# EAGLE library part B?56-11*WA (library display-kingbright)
14.22mm (0.56INCH) THREE DIGIT NUMERIC DISPLAY Source: http://www.kingbright.com .. BA56-11EWA(Ver1189474895.pdf
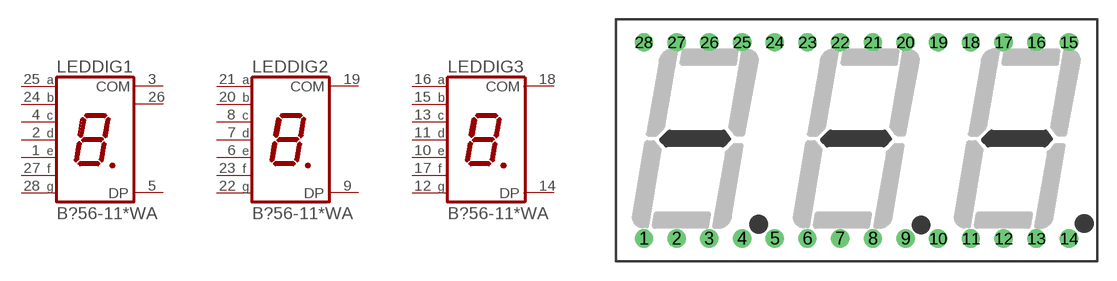
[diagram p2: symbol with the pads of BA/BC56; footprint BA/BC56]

Designator prefix LED; gates DIG2=7SEG-LED-COM1 DIG3=7SEG-LED-COM1 DIG1=7SEG-LED-COM2

## BA56-11EWA (OC_FARNELL: unknown; OC_NEWARK: unknown), BA56-11GWA (OC_FARNELL: unknown; OC_NEWARK: unknown), BA56-11SRWA (OC_FARNELL: unknown; OC_NEWARK: unknown), BA56-11YWA (OC_FARNELL: unknown; OC_NEWARK: unknown)  [BA/BC56]
1  DIG1:E  pas
2  DIG1:D  pas
3  DIG1:COM  pas
4  DIG1:C  pas
5  DIG1:DP  pas
6  DIG2:E  pas
7  DIG2:D  pas
8  DIG2:C  pas
9  DIG2:DP  pas
10  DIG3:E  pas
11  DIG3:D  pas
12  DIG3:G  pas
13  DIG3:C  pas
14  DIG3:DP  pas
15  DIG3:B  pas
16  DIG3:A  pas
17  DIG3:F  pas
18  DIG3:COM  pas
19  DIG2:COM  pas
20  DIG2:B  pas
21  DIG2:A  pas
22  DIG2:G  pas
23  DIG2:F  pas
24  DIG1:B  pas
25  DIG1:A  pas
26  DIG1:COM  pas
27  DIG1:F  pas
28  DIG1:G  pas

## BC56-11EWA (OC_FARNELL: unknown; OC_NEWARK: unknown), BC56-11GWA (OC_FARNELL: unknown; OC_NEWARK: unknown), BC56-11SRWA (OC_FARNELL: unknown; OC_NEWARK: unknown), BC56-11YWA (OC_FARNELL: unknown; OC_NEWARK: unknown)  [BA/BC56]
Pads as for BA/BC56

## Footprint BA/BC56 (pad centres in mm)
14.22mm (0.56INCH) THREE DIGIT NUMERIC DISPLAY Source: http://www.kingbright.com .. BA56-11EWA(Ver1189474895.pdf
drill 0.8 pad 1.422 round: 1 -16.51,-7.62; 2 -13.97,-7.62; 3 -11.43,-7.62; 4 -8.89,-7.62; 5 -6.35,-7.62; 6 -3.81,-7.62; 7 -1.27,-7.62; 8 1.27,-7.62; 9 3.81,-7.62; 10 6.35,-7.62; 11 8.89,-7.62; 12 11.43,-7.62; 13 13.97,-7.62; 14 16.51,-7.62; 15 16.51,7.62; 16 13.97,7.62; 17 11.43,7.62; 18 8.89,7.62; 19 6.35,7.62; 20 3.81,7.62; 21 1.27,7.62; 22 -1.27,7.62; 23 -3.81,7.62; 24 -6.35,7.62; 25 -8.89,7.62; 26 -11.43,7.62; 27 -13.97,7.62; 28 -16.51,7.62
